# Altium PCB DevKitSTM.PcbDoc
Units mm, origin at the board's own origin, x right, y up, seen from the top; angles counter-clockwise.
Board outline 101.01 x 77.01 mm, 2 copper layers (Top Layer, Bottom Layer), stack 1.571 mm thick; 95 components, 87 nets, 365 pads, 247 vias.
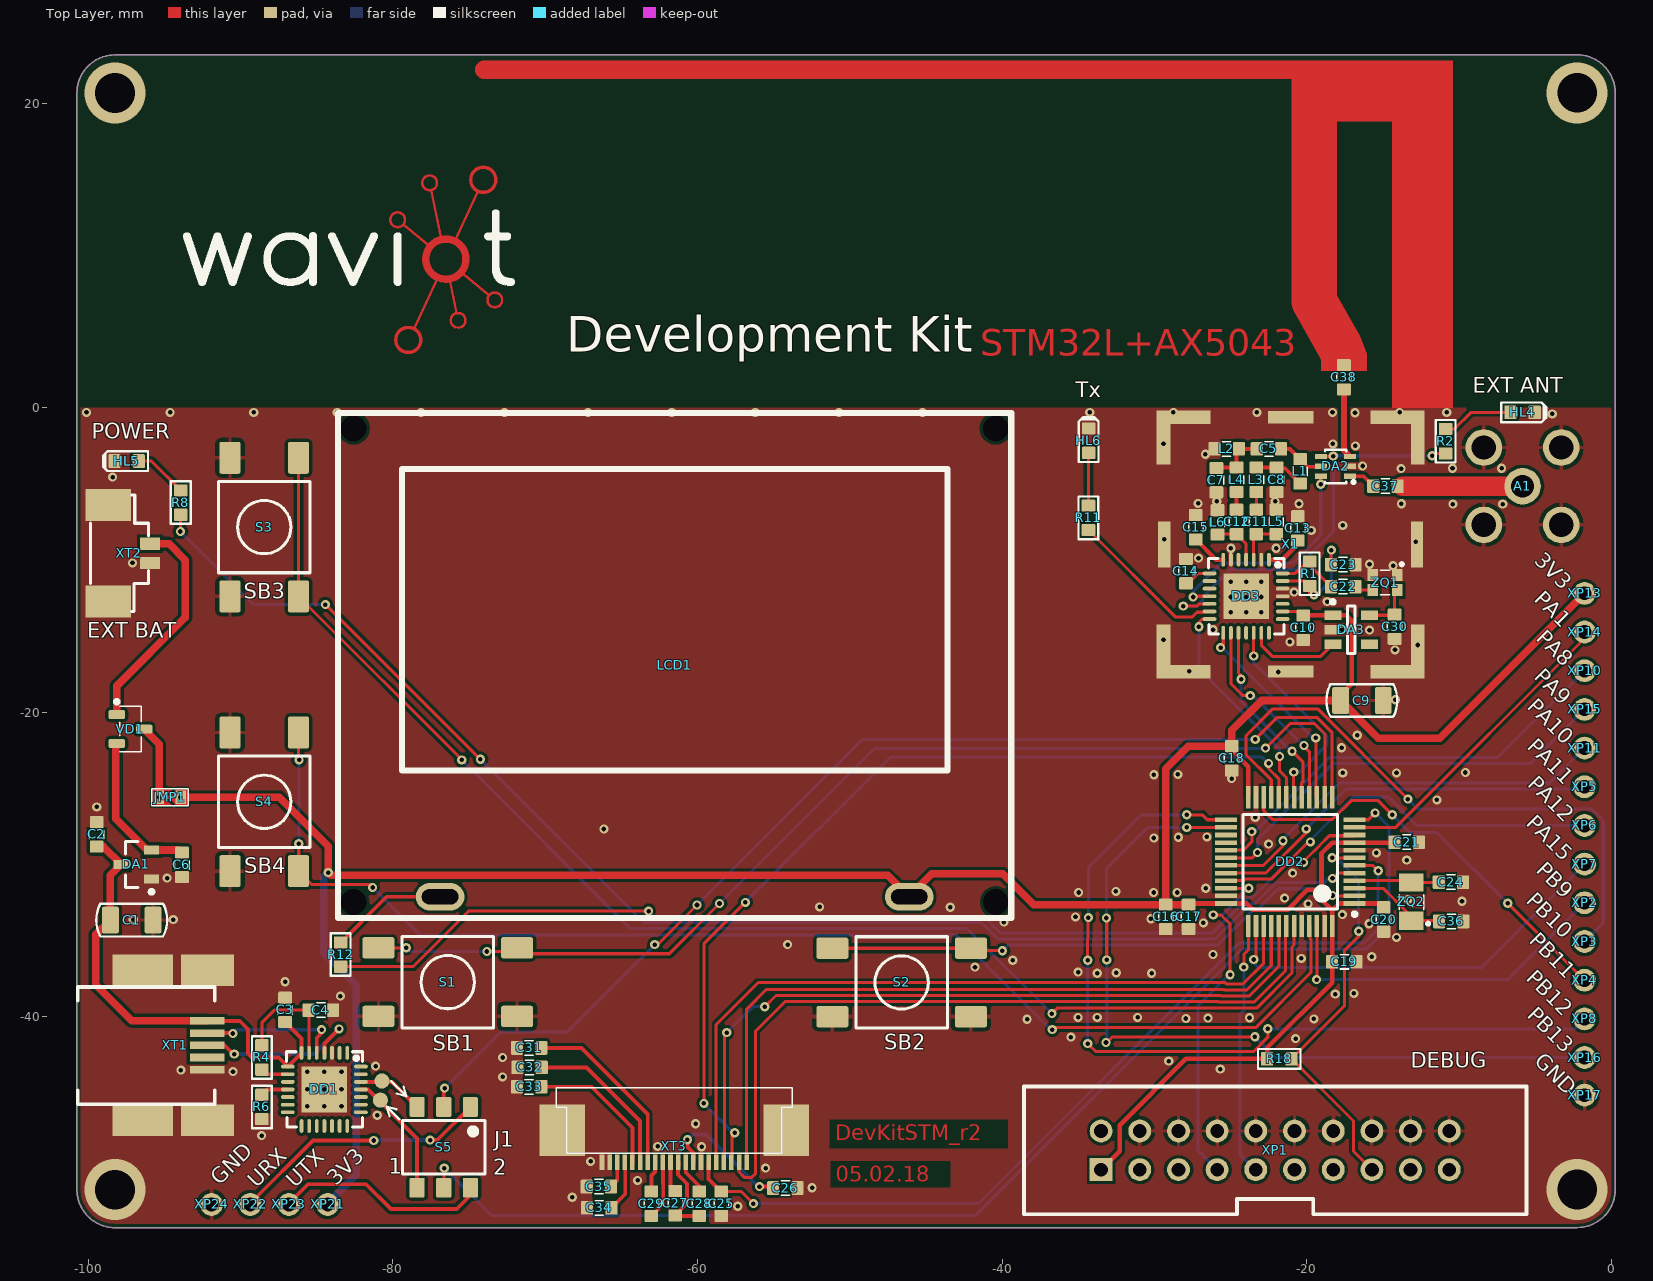
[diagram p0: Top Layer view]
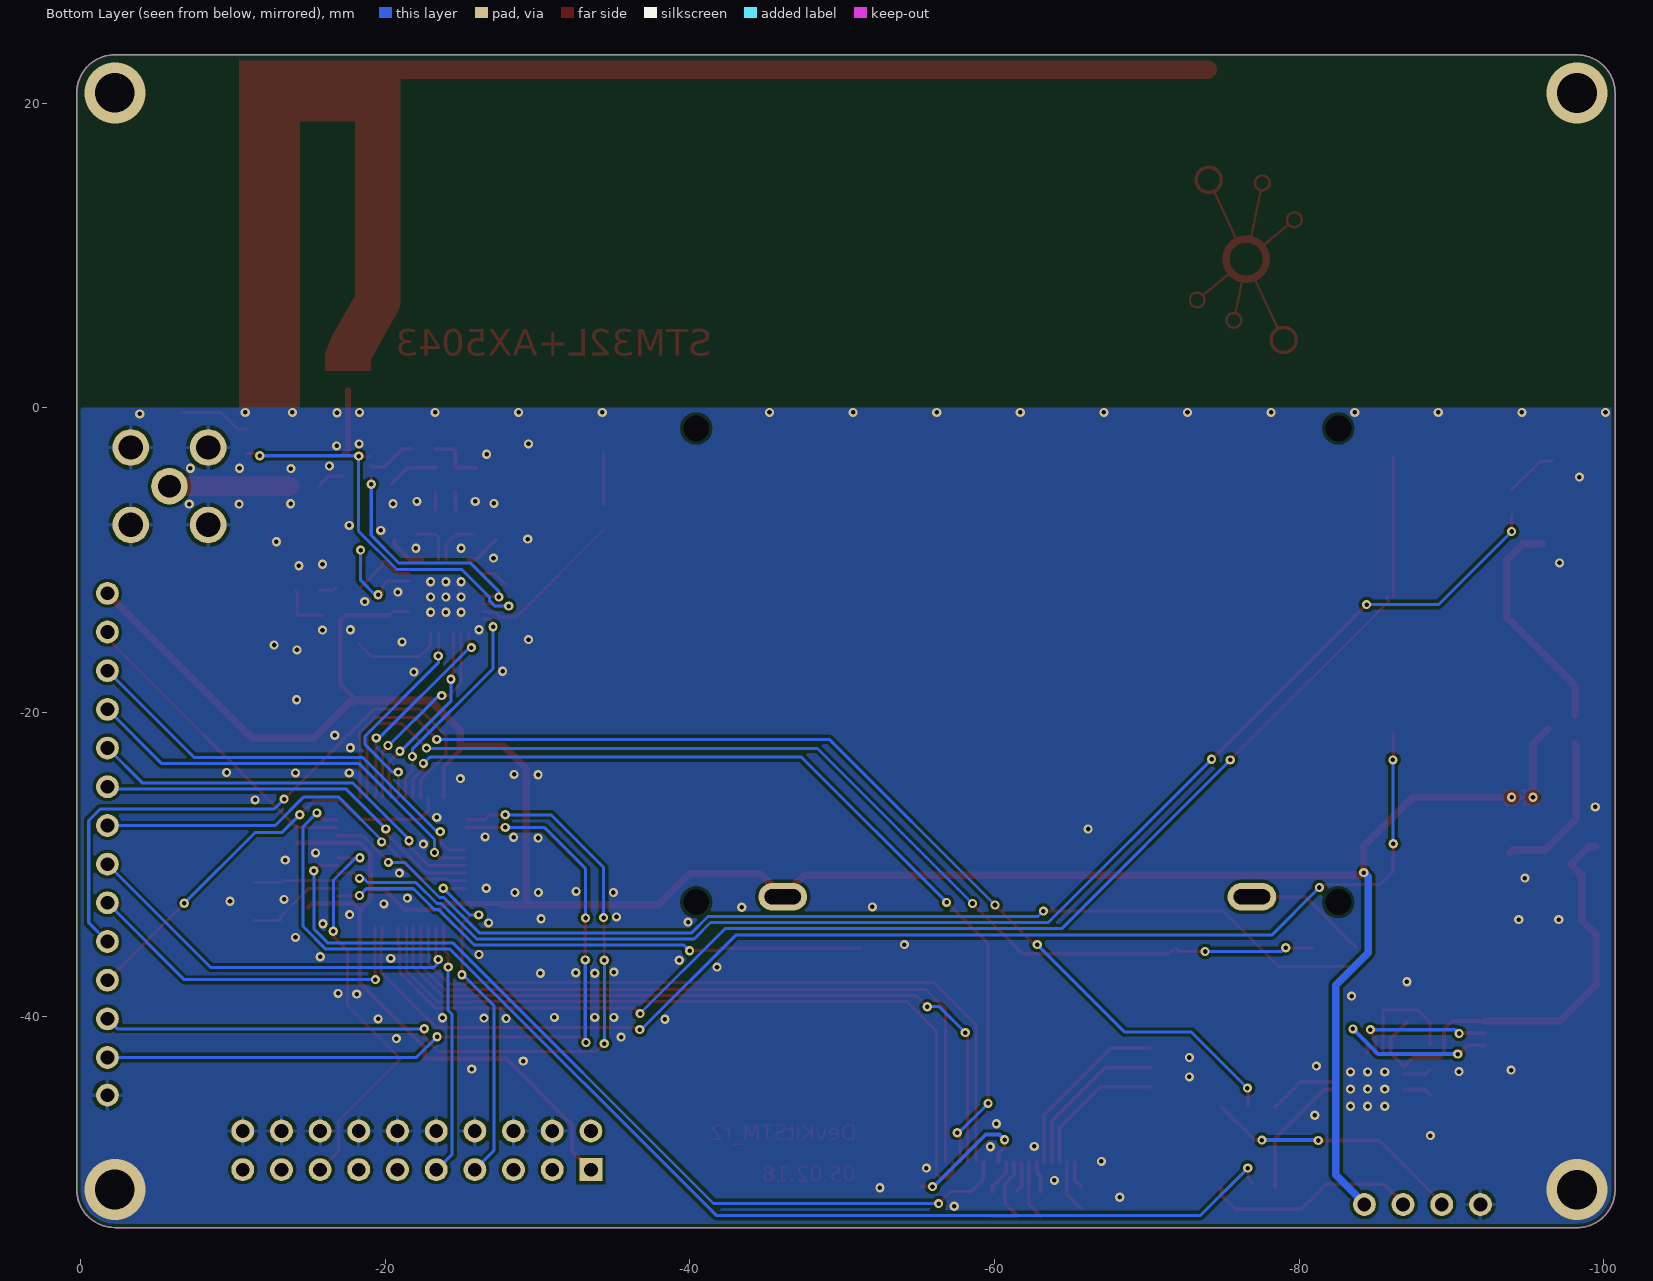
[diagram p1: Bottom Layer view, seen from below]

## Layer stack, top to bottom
Top Solder: solder mask 0.0102, Solder Resist, Dk 3.5
Top Layer: signal copper 0.0356
Dielectric 1: dielectric 1.5, FR-4, Dk 4.8
Bottom Layer: signal copper 0.0356
Bottom Solder: solder mask 0.0102, Solder Resist, Dk 3.5

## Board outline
-100.742,-51.334 -100.747,20.667 -100.742,20.667 cw(c-98.242,20.667) -98.242,23.167 -98.247,23.166 -2.242,23.166 -2.242,23.173 cw(c-2.242,20.673) 0.258,20.673 0.258,-51.328 cw(c-2.242,-51.328) -2.242,-53.828 -2.242,-53.834 -98.242,-53.834 cw(c-98.242,-51.334)

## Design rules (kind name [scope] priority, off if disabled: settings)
Clearance [All] p1: gap=0.2 ignorepadtopadclearanceinfootprint=FALSE except(0: Arc-Hole Track-Hole SMDPad-Hole THPad-Hole Via-Hole Fill-Hole Poly-Hole Region-Hole Text-Hole)
PolygonConnect PolygonConnect_1 [(HasFootprint('Cap_1206') OR HasFootprint('BH2-10') OR HasFootprint('FSM_Button') OR HasFootprint('HDR1X1') OR HasFootprint('LCD_JHD')) OR HasFootprint('SMA_Str')OR HasFootprint('BH-20')] p1: connectstyle=Relief reliefconductorwidth=0.254 reliefentries=4 polygonreliefangle="90 Angle" airgapwidth=0.254
PolygonConnect [All] p2: connectstyle=Direct reliefconductorwidth=0.3 reliefentries=4 polygonreliefangle="90 Angle" airgapwidth=0.2
RoomDefinition DevKitSTM_r1 [InComponentClass('DevKitSTM_r1')] p1: confinementstyle=ConfineIn formatcopy=TRUE lockcomponents=FALSE outline 1.425,-54.825 14.275,-54.825 14.275,24.75 1.425,24.75
RoutingVias [All] p1: holewidth=0.3 width=0.6 viastyle="Through Hole" minholewidth=0.3 minwidth=0.6 maxholewidth=1 maxwidth=1.5
SolderMaskExpansion [All] p1: expansion=0.102
Width [All] p1: maxlimit=5 minlimit=0.15 preferedwidth=0.3
30 further rules are at their usual default settings.

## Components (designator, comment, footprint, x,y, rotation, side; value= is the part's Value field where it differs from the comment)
A1 "SMA" SMA_STR -5.825,-5.15 r90 top net-tie
C1 "10 uF" CAP_1206 -97.142,-33.634 r180 top
C2 "0.1 uF" CAP_0603 -99.442,-28.009 r90 top
C3 "0.1 uF" CAP_0603 -87.072,-39.534 r90 top
C4 "0.1 uF" CAP_0603 -84.725,-39.55 r0 top
C5 "Nominal" CAP_0603 -22.475,-2.7 r180 top value="2.7 pF"
C6 "0.1 uF" CAP_0603 -93.842,-30.009 r270 top
C7 "Nominal" CAP_0603 -25.925,-4.75 r270 top value="3.6 pF"
C8 "Nominal" CAP_0603 -21.975,-4.725 r270 top value="6.2 pF"
C9 "10 uF" Cap_1206 -16.375,-19.221 r180 top
C10 "0.1uF" CAP_0603 -20.225,-14.45 r90 top
C11 "Nominal" CAP_0603 -23.3,-7.5 r270 top value="2.7 pF"
C12 "Nominal" CAP_0603 -24.6,-7.5 r270 top value="2.7 pF"
C13 "0.1uF" CAP_0603 -20.575,-7.925 r270 top
C14 "39 pF" CAP_0603 -27.925,-10.725 r270 top
C15 "0.1uF" CAP_0603 -27.275,-7.85 r270 top
C16 "Nominal" CAP_0603 -29.25,-33.425 r270 top value="4.7 uF"
C17 "Nominal" CAP_0603 -27.75,-33.425 r270 top value="0.1 uF"
C18 "Nominal" CAP_0603 -24.925,-23.019 r270 top value="0.1 uF"
C19 "Nominal" CAP_0603 -17.525,-36.375 r0 top value="0.1 uF"
C20 "Nominal" CAP_0603 -14.946,-33.6 r270 top value="0.1 uF"
C21 "Nominal" CAP_0603 -13.425,-28.525 r0 top value="0.1 uF"
C22 "1000pF" CAP_0603 -17.6,-11.75 r0 top
C23 "1000pF" CAP_0603 -17.6,-10.3 r0 top
C24 "7.5 pF" CAP_0603 -10.525,-31.15 r180 top
C25 "1uF" CAP_0603 -58.428,-52.259 r270 top
C26 "1uF" CAP_0603 -54.228,-51.234 r0 top
C27 "1uF" CAP_0603 -61.453,-52.234 r270 top
C28 "1uF" CAP_0603 -59.872,-52.259 r270 top
C29 "1uF" CAP_0603 -63.022,-52.259 r90 top
C30 "1uF" CAP_0603 -14.225,-14.375 r90 top
C31 "1uF" CAP_0603 -71.047,-42.034 r180 top
C32 "1uF" CAP_0603 -71.022,-43.309 r180 top
C33 "1uF" CAP_0603 -71.047,-44.584 r180 top
C34 "1uF" CAP_0603 -66.447,-52.534 r180 top
C35 "1uF" CAP_0603 -66.472,-51.134 r180 top
C36 "7.5 pF" CAP_0603 -10.5,-33.725 r180 top
C37 "Nominal" CAP_0603 -14.825,-5.15 r180 top value="330 pF"
C38 "Nominal" CAP_0603 -17.55,2 r270 top value="3.6 pF"
DA1 "AP2210" SOT23_L -96.842,-29.984 r180 top
DA2 "MASWSS0115" SC-70 -18.1,-3.85 r90 top
DA3 "AP2127-1.8" SOT23-5AN -17.075,-14.575 r0 top
DD1 "CP2102" QFN28 -82.992,-42.359 r270 top
DD2 "STM32L071CBT6" TSQFP50P900X900X160-48N -21.075,-29.8 r180 top
DD3 "AX5043-1-TA05" QFN28 -22.475,-9.975 r270 top
HL4 "LED_0603" LED0603 -5.825,-0.3 r180 top
HL5 "LED_0603" LED0603 -97.475,-3.5 r0 top
HL6 "LED_0603" LED0603 -34.309,-2.158 r270 top
JMP1 "STD_RES" JMP_PCB -94.625,-25.575 r0 top value="PCB Jumper"
L1 "STD_IND" IND_0603 -20.425,-4.175 r270 top value="12 nH"
L2 "STD_IND" IND_0603 -25.25,-2.7 r0 top value="12 nH"
L3 "STD_IND" IND_0603 -23.3,-4.725 r270 top value="18 nH"
L4 "STD_IND" IND_0603 -24.6,-4.725 r270 top value="18 nH"
L5 "STD_IND" IND_0603 -22,-7.5 r90 top value="18 nH"
L6 "STD_IND" IND_0603 -25.85,-7.525 r90 top value="18 nH"
LCD1 "LCD_JHD" LCD_JHD -83.592,-33.509 r0 top locked
R1 "1k" RES_0603 -19.8,-10.9 r270 top
R2 "1k" RES_0603 -10.875,-2.2 r90 top
R4 "10k" RES_0603 -88.597,-42.659 r90 top
R6 "10k" RES_0603 -88.597,-45.909 r90 top
R8 "100" RES_0603 -93.925,-6.225 r90 top
R11 "1k" RES_0603 -34.325,-7.225 r90 top
R12 "20" RES_0603 -83.425,-35.9 r90 top
R18 "1k" RES_0603 -21.8,-42.75 r180 top
S1 "SMD Button" FSM_BUTTON -76.392,-37.709 r270 top locked
S2 "SMD Button" FSM_BUTTON -46.592,-37.734 r270 top
S3 "SMD Button" FSM_BUTTON -88.442,-7.834 r180 top locked
S4 "SMD Button" FSM_Button -88.442,-25.875 r180 top locked
S5 "CAS-220" CAS-220 -76.653,-48.559 r180 top
VD1 "PMEG2005CT" SOT23 -97.225,-21.1 r0 top
X1 "STD_CON1" BMI-S-202-F -21.05,-8.975 r0 top locked
XP1 "Debug Connector" BH-20 -22.065,-48.755 r0 top
XP2 "PLS-1" HDR1X1#1 -1.75,-32.505 r180 top
XP3 "PLS-1" HDR1X1#1 -1.75,-35.045 r180 top
XP4 "PLS-1" HDR1X1#1 -1.75,-37.585 r180 top
XP5 "PLS-1" HDR1X1#1 -1.75,-24.885 r180 top
XP6 "PLS-1" HDR1X1#1 -1.75,-27.425 r180 top
XP7 "PLS-1" HDR1X1#1 -1.75,-29.965 r180 top
XP8 "PLS-1" HDR1X1#1 -1.75,-40.125 r180 top
XP10 "PLS-1" HDR1X1#1 -1.75,-17.265 r180 top
XP11 "PLS-1" HDR1X1#1 -1.75,-22.345 r180 top
XP13 "PLS-1" HDR1X1#2 -1.75,-22.562 r180 top
XP14 "PLS-1" HDR1X1#1 -1.75,-14.725 r180 top
XP15 "PLS-1" HDR1X1#1 -1.75,-19.805 r180 top
XP16 "PLS-1" HDR1X1#1 -1.75,-42.665 r180 top
XP17 "PLS-1" HDR1X1#3 -1.75,-50.492 r180 top
XP21 "PLS-1" HDR1X1#4 -89.679,-52.334 r90 top
XP22 "PLS-1" HDR1X1#5 -89.359,-52.334 r90 top
XP23 "PLS-1" HDR1X1#1 -86.819,-52.309 r90 top
XP24 "PLS-1" HDR1X1#6 -91.753,-52.359 r90 top
XT1 "Molex_MINIUSB" MOLEX_MINIUSB -96.417,-46.784 r0 top
XT2 "Molex053047" MOLEX0533980271 -95.942,-8.934 r270 top
XT3 "Molex0527462071" MOLEX_0527462071 -56.767,-49.534 r180 top locked
ZQ1 "NT2016SA-26MHz" NT2016SA -14.85,-11.475 r0 top
ZQ2 "KX-327NHT" KX-327NHT -13.125,-32.475 r90 top

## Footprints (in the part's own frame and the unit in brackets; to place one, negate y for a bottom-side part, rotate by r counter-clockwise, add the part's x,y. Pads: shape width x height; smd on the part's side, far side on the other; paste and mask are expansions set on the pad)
BH-20 [mm]
  rect 1.5x1.5 hole 0.9: 1(-11.43,-1.27)
  round 1.5 hole 0.9: 2(-11.43,1.27) 3(-8.89,-1.27) 5(-6.35,-1.27) 7(-3.81,-1.27) 9(-1.275,-1.27) 11(1.27,-1.27) 13(3.81,-1.27) 15(6.35,-1.27) 17(8.885,-1.27) 19(11.43,-1.27) G(-8.89,1.27) G(-6.35,1.27) G(-3.81,1.27) G(-1.275,1.27) G(1.27,1.27) G(3.81,1.27) G(6.35,1.27) G(8.885,1.27) G(11.43,1.27)
  silkscreen extent -16.5,-4.2 16.5,4.2, body extent -16.51,-4.8 16.51,4.8, height 9.2
BMI-S-202-F [mm]
  rect 0.9x0.9 smd mask+0.05: 1(-8.35,-8.35) 1(-8.35,8.35) 1(8.35,-8.35) 1(8.35,8.35)
  rect 0.9x2.7 smd mask+0.05: 1(-8.35,-6.6) 1(-8.35,6.6) 1(8.35,-6.6) 1(8.35,6.6)
  rect 0.8x3 smd mask+0.05: 1(-8.3,0) 1(8.3,0)
  rect 2.7x0.9 smd mask+0.05: 1(-6.6,8.35) 1(-6.6,-8.35) 1(6.6,8.35) 1(6.6,-8.35)
  rect 3x0.8 smd mask+0.05: 1(0,-8.35) 1(0,8.35)
  body extent -8.25,-8.25 8.25,8.25, height 3.7
CAP_0603 [mm]
  rrect20% 0.8x0.9 smd: 1(-0.8,0) 2(0.8,0)
  Top Layer pour cut-out: -0.425,0.65 0.45,0.65 0.45,-0.65 -0.425,-0.65
  silkscreen extent -0.28,-0.48 0.28,0.48, body extent -0.88,-0.48 0.87,0.48, height 0.85
CAP_1206 [mm]
  rrect20% 1.1x1.75 smd: 1(-1.4,0) 2(1.4,0)
  silkscreen extent -2.33,-1.07 2.33,1.08, body extent -1.65,-0.9 1.65,0.9, height 1.35
Cap_1206 [mm]
  rrect20% 1.1x1.75 smd: 1(-1.4,0) 2(1.4,0)
  silkscreen extent -2.33,-1.07 2.33,1.08, body extent -1.65,-0.9 1.65,0.9, height 1.35
CAS-220 [mm]
  rrect20% 1x1.3 smd: 1(-1.75,-2.65) 2(0,-2.65) 3(1.75,-2.65) 4(-1.75,2.65) 5(0,2.65) 6(1.75,2.65)
  silkscreen extent -2.7,-1.75 2.7,1.75, body extent -2.7,-2.72 2.7,2.88, height 2.5
FSM_BUTTON [mm]
  rrect20% 1.4x2.1 smd: 1(-2.25,4.55) 1(-2.25,-4.55) 2(2.25,4.55) 2(2.25,-4.55)
  silkscreen extent -3,-3 3,3, body extent -3,-3 3,3, height 5
FSM_Button [mm]
  rrect20% 1.4x2.1 smd: 1(-2.25,4.55) 1(-2.25,-4.55) 2(2.25,4.55) 2(2.25,-4.55)
  silkscreen extent -3,-3 3,3, body extent -3,-3 3,3, height 5
HDR1X1#1 [mm]
  round 1.5 hole 0.9 mask+0: 1(0,0)
HDR1X1#2 [mm]
  round 1.5 hole 0.9 mask+0: 1(0,-10.377)
HDR1X1#3 [mm]
  round 1.5 hole 0.9 mask+0: 1(0,-5.362)
HDR1X1#4 [mm]
  round 1.5 hole 0.9 mask+0: 1(0.025,-5.4)
HDR1X1#5 [mm]
  round 1.5 hole 0.9 mask+0: 1(0.025,0)
HDR1X1#6 [mm]
  round 1.5 hole 0.9 mask+0: 1(0.05,0.146)
IND_0603 [mm]
  rrect20% 0.8x0.9 smd: 1(-0.8,0) 2(0.8,0)
  Top Layer pour cut-out: -0.425,0.65 0.45,0.65 0.45,-0.65 -0.425,-0.65
  silkscreen extent -0.28,-0.48 0.28,0.48, body extent -0.88,-0.48 0.87,0.48, height 0.85
JMP_PCB [mm]
  rect 0.6x0.9 smd: 1(-0.7,0)
  rect 0.7x0.9 smd: 2(0.7,0)
  Top Layer region: -0.1,0 0.408,0.508 1.143,0.508 1.143,-0.508 0.408,-0.508
  Top Layer region: 0.108,0.508 -0.4,0 0.108,-0.508 -1.143,-0.508 -1.143,0.508
  silkscreen extent -1.2,-0.55 1.2,0.55
KX-327NHT [mm]
  rect 1.2x1.6 smd mask+0.05: 1(-1.2,0) 2(1.3,0)
  silkscreen extent -1.5,-1.2 0.5,0.8, body extent -1.6,-0.75 1.6,0.75, height 0.8
LCD_JHD [mm]
  oval 3.2x1.8 hole 1 slot 2.4 at 0 deg: A(37.5,1.4) K(6.7,1.4)
  round 0 hole 1.7 unplated: ""(1.02,1.05) ""(1.02,32.15) ""(43.18,1.05) ""(43.18,32.15)
  silkscreen extent 0,0 44.2,33.18, body extent 0,0 44.23,33.18, height 4
LED0603 [mm]
  rrect20% 0.8x0.9 smd: A(0.8,0) C(-0.8,0)
  silkscreen extent -1.55,-0.65 1.4,0.65, body extent -0.8,-0.4 0.8,0.4, height 0.28
MOLEX0533980271 [mm]
  rect 0.8x1.3 smd mask+0.05: 1(0,0) 2(1.25,0)
  rect 2.1x3 smd mask+0.05: 3(-2.55,-2.75) 3(3.8,-2.75)
  silkscreen extent -3.2,-3.9 4.45,-0.1, body extent -3.18,-3.95 4.47,0.25, height 4.6
MOLEX_0527462071 [mm]
  rect 0.3x1 smd mask+0.05: 1(0,0) 2(0.5,0) 3(1,0) 4(1.5,0) 5(2,0) 6(2.5,0) 7(3,0) 8(3.5,0) 9(4,0) 10(4.5,0) 11(5,0) 12(5.5,0) 13(6,0) 14(6.5,0) 15(7,0) 16(7.5,0) 17(8,0) 18(8.5,0) 19(9,0) 20(9.5,0)
  rect 3x3.4 smd mask+0.05: 21(-2.6,-2.1) 22(12.1,-2.1)
  silkscreen extent -3,-4.9 12.5,-0.6, body extent -3.3,-6.42 12.8,0.18, height 2
MOLEX_MINIUSB [mm]
  rect 2.25x0.5 smd mask+0.05: 1(4.225,6.525) 2(4.225,5.725) 3(4.225,4.925) 4(4.225,4.125) 5(4.225,3.325)
  rect 4x2.05 smd mask+0.05: 5(0,0) 5(0,9.85)
  rect 3.5x2.05 smd mask+0.05: 5(4.25,0) 5(4.25,9.85)
  silkscreen extent -4.28,1.05 4.72,8.75, body extent -4.27,0 4.72,9.9, height 4.05
NT2016SA [mm]
  rect 0.7x0.8 smd mask+0.05: 1(0.795,0.5) 2(-0.805,0.5) 3(-0.805,-0.5) 4(0.795,-0.5)
  silkscreen extent -0.31,-0.8 1.19,1.3, body extent -1,-0.8 1,0.8, height 0.8
QFN28 [mm]
  oval 0.9x0.25 smd: 1(0,0) 2(0,-0.5) 3(0,-1) 4(0,-1.5) 5(0,-2) 6(0,-2.5) 7(0,-3) 15(4.8,-3) 16(4.8,-2.5) 17(4.8,-2) 18(4.8,-1.5) 19(4.8,-1) 20(4.8,-0.5) 21(4.8,0)
  oval 0.25x0.9 smd: 8(0.9,-3.9) 9(1.4,-3.9) 10(1.9,-3.9) 11(2.4,-3.9) 12(2.9,-3.9) 13(3.4,-3.9) 14(3.9,-3.9) 22(3.9,0.9) 23(3.4,0.9) 24(2.9,0.9) 25(2.4,0.9) 26(1.9,0.9) 27(1.4,0.9) 28(0.9,0.9)
  rect 3x3 smd mask+0: 29(2.4,-1.5)
  silkscreen extent -0.08,-3.98 4.88,1, body extent -0.1,-3.95 4.9,1.05, height 1
RES_0603 [mm]
  rrect20% 0.8x0.9 smd: 1(-0.8,0) 2(0.8,0)
  Top Layer pour cut-out: -0.425,0.65 0.45,0.65 0.45,-0.65 -0.425,-0.65
  silkscreen extent -1.4,-0.65 1.4,0.65, body extent -0.85,-0.48 0.85,0.48, height 0.6
SC-70 [mm]
  rect 0.35x0.8 smd mask+0.05: 1(-0.65,-0.95) 2(0,-0.95) 3(0.65,-0.95) 4(0.65,0.95) 5(0,0.95) 6(-0.65,0.95)
  silkscreen extent -1.12,-1.27 1.1,0.7, body extent -1,-1.05 1,1.05, height 0.92
SMA_STR [mm]
  round 2.4 hole 1.5: 1(0,0)
  round 2.4 hole 1.6: 2(-2.54,-2.54) 2(-2.54,2.54) 2(2.54,-2.54) 2(2.54,2.54)
  body extent -3.17,-3.18 3.18,3.18, height 10.22
SOT23 [mm]
  rrect50% 1.1x0.6 smd: 1(-0.9,0.95) 2(-0.9,-0.95) 3(0.9,0)
  silkscreen extent -1.02,-1.5 0.7,1.92, body extent -1.25,-1.5 1.25,1.5, height 1.06
SOT23-5AN [mm]
  rect 1.1x0.65 smd: 1(-1.2,0.95) 2(-1.2,0) 3(-1.2,-0.95) 4(1.2,-0.95) 5(1.2,0.95)
  silkscreen extent -1.32,-1.55 0.25,1.95, body extent -1.5,-1.5 1.5,1.5, height 1.3
SOT23_L [mm]
  rect 1x0.6 smd: 1(-1,0.95) 2(-1,-0.95) 3(1,0)
  silkscreen extent -1.13,-1.5 0.7,1.92, body extent -1.32,-1.5 1.32,1.5, height 1.08
TSQFP50P900X900X160-48N [mm]
  rect 1.45x0.3 smd: 1(-4.225,2.75) 2(-4.225,2.25) 3(-4.225,1.75) 4(-4.225,1.25) 5(-4.225,0.75) 6(-4.225,0.25) 7(-4.225,-0.25) 8(-4.225,-0.75) 9(-4.225,-1.25) 10(-4.225,-1.75) 11(-4.225,-2.25) 12(-4.225,-2.75) 25(4.225,-2.75) 26(4.225,-2.25) 27(4.225,-1.75) 28(4.225,-1.25) 29(4.225,-0.75) 30(4.225,-0.25) 31(4.225,0.25) 32(4.225,0.75) 33(4.225,1.25) 34(4.225,1.75) 35(4.225,2.25) 36(4.225,2.75)
  rect 0.3x1.45 smd: 13(-2.75,-4.225) 14(-2.25,-4.225) 15(-1.75,-4.225) 16(-1.25,-4.225) 17(-0.75,-4.225) 18(-0.25,-4.225) 19(0.25,-4.225) 20(0.75,-4.225) 21(1.25,-4.225) 22(1.75,-4.225) 23(2.25,-4.225) 24(2.75,-4.225) 37(2.75,4.225) 38(2.25,4.225) 39(1.75,4.225) 40(1.25,4.225) 41(0.75,4.225) 42(0.25,4.225) 43(-0.25,4.225) 44(-0.75,4.225) 45(-1.25,4.225) 46(-1.75,4.225) 47(-2.25,4.225) 48(-2.75,4.225)
  silkscreen extent -4.35,-3.1 3.1,3.57, body extent -3.5,-3.5 3.5,3.5, height 1.6

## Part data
A1: library part SMA_Str, "CONN SMA JACK STR 50 OHM PCB", PartNumber=5-1814832-1
C1 C9: library part "Cap 1206", "CAP CER 10UF 16V Y5V 1206", Code Value="code of resistance marked on chip", Package=Footprint, PartNumber=CL31F106ZOHNNNE
C2 C3 C4 C6 C10 C13 C15: library part "Cap 0603", "CAP CER 0603 0.1 uF 16 V 10% X7R", Code Value="code of resistance marked on chip", Package=Footprint, PartNumber=CC0603KRX7R7BB104
C5 C11 C12: library part GRM1885C1H2R7CA01D, "CAP CER 2.7PF 50V NPO 0603", Manufacturer=MURATA, PartNumber=CC0603BRNPO9BN2R7, Tolerance="+/- 0.25 пФ"
C7 C38: library part CL10C3R6CB8NNNC, "CAP CER 3.6PF 50V NPO 0603", Manufacturer=Samsung, PartNumber=CC0603BRNPO9BN3R6, Tolerance="+/- 0.25 пФ"
C8: library part CL10C6R2CB8NNNC, "CAP CER 6.2PF 50V NPO 0603", Manufacturer=Samsung, Tolerance="+/- 0.25 пФ"
C14: library part "Cap 0603", "CAP CER 39PF 50V C0G/NPO 0603", Code Value="code of resistance marked on chip", Package=Footprint, PartNumber=CC0603JRNPO9BN390
C16: library part CC0603KRX5R6BB475, "CAP CER 0603 4.7 uF 10 V 10% X5R", Manufacturer=YAGEO, Tolerance=10%
C17 C18 C19 C20 C21: library part CC0603KRX7R7BB104, "CAP CER 0603 0.1 uF 16 V 10% X7R", Manufacturer=YAGEO, Tolerance=10%
C22 C23: library part "Cap 0603", "CAP CER 1000PF 50V X7R 0603", Code Value="code of resistance marked on chip", Package=Footprint, PartNumber=CC0603KRX7R9BB102
C24 C36: library part "Cap 0603", "CAP CER 7.5PF 50V NPO 0603", Code Value="code of resistance marked on chip", Package=Footprint, PartNumber=CC0603CRNPO9BN7R5
C25 C26 C27 C28 C29 C31 C32 C33 C34 C35: library part "Cap 0805", "CAP CER 1UF 16V X7R 0603", Code Value="code of resistance marked on chip", Package=Footprint, PartNumber=CC0603KRX7R7BB105
C30: library part "Cap 0603", "CAP CER 1UF 16V X7R 0603", Code Value="code of resistance marked on chip", Package=Footprint, PartNumber=CC0603KRX7R7BB105
C37: library part GRM1885C1H2R7CA01D, "CAP CER 330PF 50V NPO 0603", Manufacturer=MURATA, PartNumber=CC0603JRNPO9BN331, Tolerance="+/- 0.25 пФ"
DA1: "IC REG LDO 3.3V 0.3A SOT23", PartNumber=AP2210N-3.3TRG1
DA2: "GaAs SPDT Switch  DC - 3.0 GHz", PartNumber=MASWSS0115TR-3000
DA3: library part AP2127, "IC REG LINEAR 1.8V 300MA SOT23-5", PartNumber=AP2127K-1.8TRG1
DD1: "IC USB-TO-UART BRIDGE 28VQFN", PartNumber=CP2102-GMR
DD2: "IC MCU 32BIT 128KB FLASH 48LQFP", Digi-Key Part Number=STM32L071CBT6-ND, Manufacturer=STMicroelectronics, Operating Temperature="-40°C ~ 85°C (TA)", Package / Case=48-LQFP, Voltage - Supply (Vcc/Vdd)="1.65 V ~ 3.6 V"
DD3: library part AX5043, "IC AXSEM RF Tranceiver"
HL4: "LED GREEN CLEAR 0603 SMD", PartNumber=APT1608CGCK
HL5: "LED 527NM BLU/GRN TRANSP RA SMD", PartNumber=SMLE13EC8TT86
HL6: "LED 1.6X0.8MM 630NM RED CLR SMD", PartNumber=APT1608SURCK
JMP1: library part JMP_PCB, "NoName  PCB Jumper", Manufacturer=NoName
L1: library part LQW18AN12NG00, "FIXED IND 18NH 650MA 160 MOHM", Current="650 мА", Manufacturer=MURATA, Tolerance=2%
L2: library part LQW18AN12NG00, "FIXED IND 12NH 650MA 160 MOHM", Current="650 мА", Manufacturer=MURATA, Tolerance=2%
L3 L4 L5 L6: library part LQW18AN18NG00, "FIXED IND 18NH 550MA 160 MOHM", Current="500 мА", Manufacturer=MURATA, Tolerance=2%
LCD1: "LCD Display", PartNumber=JHD12864
R1 R2 R11 R18: library part "Res 0603", "RES SMD 1K OHM 1% 1/10W 0603", Code Value="code of resistance marked on chip", Package=Footprint, PartNumber=RC1608F102CS
R4 R6: library part "Res 0603", "RES SMD 10 KOHM 1% 1/10W 0603", Code Value="code of resistance marked on chip", Package=Footprint, PartNumber=RC1608F103CS
R8: library part "Res 0603", "RES SMD 100 OHM 1% 1/10W 0603", Code Value="code of resistance marked on chip", Package=Footprint, PartNumber=RC1608J101CS
R12: library part "Res 0805", "RES SMD 20 OHM 1% 1/10W 0603", Code Value="code of resistance marked on chip", Package=Footprint, PartNumber=RC1608F200CS
S1 S2 S3 S4: "SWITCH TACTILE SPST-NO 0.05A 24V", PartNumber=FSM4JSMATR
S5: "SLIDE SWITCH DPDT GULLWING 6V", PartNumber=CAS-220TB
VD1: "DIODE ARRAY SCHOTTKY 20V SOT23", Current="500 мА", Manufacturer=NXP
X1: library part BMI-S-202-F, "BOARD SHIELD .65X.65\" FRAME + COVER", Manufacturer=Liard, PartNumber="BMI-S-202-F + BMI-S-202-C"
XP1: library part JTAG_BH20, "CONN 2 RAWS 20 PINS 2.54 PITCH", PartNumber=BH-20
XT1: "CONN RECEPT MINIUSB R/A 5POS SMD", PartNumber=548190572
XT2: "CONN HEADER 2POS 1.25MM VERT SMD", PartNumber=533980271
XT3: "20-pin LCD connector", PartNumber=CONN_FOR_JHD12864
ZQ1: library part NT2016, "Quartz Crystal Controlled Oscillator", PartNumber=NT2016SA-26.000000MHZ-NBG2
ZQ2: "Geyer  Quartz Crystal", Part Manufacturer="GEYER ELECTRONIC"

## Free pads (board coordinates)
  round 1 smd mask+0: 1(-80.817,-45.459) 1(-80.717,-44.209)

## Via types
v1: diameter 0.6, hole 0.3, Top Layer to Bottom Layer, tented both sides, 243 vias
v2: diameter 4, hole 2.6, Top Layer to Bottom Layer, 4 vias

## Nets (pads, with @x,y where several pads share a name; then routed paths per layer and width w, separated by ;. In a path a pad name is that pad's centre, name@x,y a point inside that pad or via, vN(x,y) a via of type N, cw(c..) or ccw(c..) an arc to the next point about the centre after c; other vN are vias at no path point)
GND: A1.2 C1.1 C2.2 C3.2 C4.2 C6.2 C7.2 C8.2 C9.1 C10.1 C13.1 C14.1 C15.1 C16.2 C17.2 C18.2 C19.2 C20.2 C21.2 C23.2 C24.1 C25.2 C26.2 C30.1 C31.2 C32.2 C33.2 C34.2 C35.2 C36.1 C38.1 DA1.1 DA2.2 DA3.2 DD1.3 DD1.29 DD2.8 DD2.23 DD2.35 DD2.44 DD2.47 DD3.2 DD3.6 DD3.25 DD3.26 DD3.29 HL4.C HL5.C HL6.C L2.1 L5.2 L6.2 R6.1 S1.2 S2.2 S3.2 S4.2 X1.1 XP1.G XP17.1 XP24.1 XT1.5 XT2.2 XT2.3 XT3.7 XT3.19 XT3.20 XT3.21 XT3.22 ZQ1.1 ZQ1.2 | length 68.5
  Top Layer w1.2: -74,22.2 -21,22.2
  Top Layer w3: -19.5,19 -19.5,7 -17.791,3.933
  other v1: -57.35,-52.425 -68.217,-51.834 -52.467,-51.209 -63.925,-50.725 -55.525,-49.925 -67.017,-49.484 -59.725,-48.525 -62.6,-48.5 -88.617,-47.784 -60.117,-47.009 -81.025,-46.45 -85.617,-45.859 -84.492,-45.859 -83.367,-45.859 -85.617,-44.734 -84.492,-44.734 -83.367,-44.734 -72.792,-43.934 -85.617,-43.609 -84.492,-43.609 -83.367,-43.609 -90.492,-43.584 -93.917,-43.484 -25.675,-43.425 -81.125,-43.225 -29.05,-42.9 -72.792,-42.659 -20.725,-41.425 -35.475,-41.325 -38.35,-40.15 -19.525,-40.125 -27.925,-40.1 -26.475,-40.075 -23.75,-40.05 -35,-40.025 -33.75,-40.025 -31.1,-40.025 -83.442,-38.634 -18.125,-38.5 -16.9,-38.45 -87.067,-37.684 -33.75,-37.125 -32.5,-37.1 -30.175,-37.125 -35,-37.05 -41.775,-36.725 -39.3,-36.275 -20.35,-36.15 -15.725,-36.05 -26.15,-35.9 -54.075,-35.25 -14.1,-34.775 -15.9,-33.875 -26.775,-33.825 -39.875,-33.775 -97.042,-33.609 -94.417,-33.609 -30.225,-33.55 -35.175,-33.425 -17.65,-33.275 -43.4,-32.8 -51.975,-32.775 -19.9,-32.575 -9.8,-32.4 -13.35,-32.275 -21.45,-32.2 -34.975,-31.825 -30.05,-31.825 -28.5,-31.825 -32.525,-31.75 -26.625,-31.55 -94.817,-30.884 -20.925,-30.55 -13.425,-29.7 -15.425,-29.225 -22.5,-28.65 -30.025,-28.25 -28.425,-28.2 -26.55,-28.175 -66.142,-27.659 -23.375,-26.9 -99.442,-26.209 -11.45,-25.75 -24.925,-24.35 -30.025,-24.1 -28.45,-24.075 -17.625,-23.975 -14.1,-23.975 -9.575,-23.95 -17.7,-22.325 -16.675,-21.5 -14.175,-19.175 -21.875,-17.35 -27.7,-17.3 -14.2,-15.9 -12.7,-15.575 -21.1,-15.375 -29.4,-15.225 -15.875,-14.6 -26.15,-14.575 -17.7,-14.575 -24.975,-13.425 -23.975,-13.425 -22.975,-13.425 -18.65,-12.725 -24.975,-12.425 -23.975,-12.425 -22.975,-12.425 -20.825,-12.1 -24.975,-11.425 -23.975,-11.425 -22.975,-11.425 -14.325,-10.375 -15.875,-10.275 -97.092,-10.184 -27.1,-9.875 -24.975,-9.225 -22,-9.225 -12.85,-8.8 -29.35,-8.625 -19.7,-8.05 -17.625,-7.725 -10.4,-6.325 -7.125,-6.325 -20.5,-6.3 -13.775,-6.3 -27.125,-6.275 -25.9,-6.15 -22.075,-6.15 -98.4,-4.55 -13.8,-4 -10.425,-3.975 -7.2,-3.975 -16.325,-3.825 -26.65,-3.05 -16.8,-2.5 -29.4,-2.375 -18.275,-2.375 -3.875,-0.4 -16.825,-0.325 -100.113,-0.3 -94.623,-0.3 -89.134,-0.3 -83.645,-0.3 -78.156,-0.3 -72.667,-0.3 -67.178,-0.3 -61.688,-0.3 -56.199,-0.3 -50.71,-0.3 -45.221,-0.3 -34.243,-0.3 -28.753,-0.3 -23.264,-0.3 -18.3,-0.3 -13.9,-0.3 -10.8,-0.3
  other v2: -98.242,-51.334 -2.242,-51.328
NetA1_1: A1.1 C37.1 | length 7.9
  Top Layer w1.3: C37.1@-13.7,-5.15 A1.1
NetC1_2: C1.2 C2.1 C3.1 DA1.3 DD1.7 DD1.8 XT1.1 | length 30.2
  Top Layer w0.25: XT1.1 -90.053,-40.259 -89.503,-40.809 -89.503,-42.39 -89.234,-42.659 -87.492,-42.659 DD1.8 DD1.7 -85.992,-41.414 C3.1
  Top Layer w0.5: C2.1 -99.017,-28.809 DA1.3 -98.542,-30.684 C1.2 -99.492,-34.584 -99.492,-37.896 -97.128,-40.259 XT1.1
NetC4_1: C4.1 DD1.6 R4.2 | length 7.7
  Top Layer w0.2: R4.2 -88.597,-40.372 -87.775,-39.55 C4.1 ; DD1.6 C4.1@-85.492,-39.55
NetC5_1: C5.1 DA2.5 L1.1 | length 3.1
  Top Layer w0.25: C5.1 -21.1,-2.7 L1.1 -19.925,-3.875 -19.075,-3.875 DA2.5
NetC5_2: C5.2 C7.1 L2.2 L4.1 | length 3.8
  Top Layer w0.25: C7.1 -25.9,-3.925 L4.1 -24.6,-2.85 L2.2 C5.2
NetC6_1: C6.1 DA1.2 VD1.2 | length 10.2
  Top Layer w0.5: VD1.2 -98.2,-22.125 -98.2,-26.975 -96.141,-29.034 DA1.2 -94.017,-29.034 C6.1
NetC8_1: C8.1 L1.2 L3.1 | length 3.3
  Top Layer w0.25: L3.1 -22.025,-3.925 -21.975,-3.975 -21.425,-3.975 L1.2
NetC11_1: C11.1 L3.2 | length 1.2
  Top Layer w0.2: C11.1 L3.2
NetC11_2: C11.2 DD3.3 L5.1 | length 3
  Top Layer w0.2: DD3.3 -23.475,-8.475 C11.2 L5.1
NetC12_1: C12.1 L4.2 | length 1.2
  Top Layer w0.28: C12.1 L4.2
NetC12_2: C12.2 DD3.4 L6.1 | length 3.2
  Top Layer w0.2: L6.1 -25.825,-8.3 C12.2 -23.975,-8.925 DD3.4
NetC13_2: C13.2 DD3.1 | length 2.5
  Top Layer w0.3: DD3.1@-22.425,-9.975 -21.6,-9.975 -20.575,-8.95 C13.2
NetC14_2: C14.2 DD3.8 | length 1.8
  Top Layer w0.2: C14.2 -27.775,-11.525 -27.125,-10.875 DD3.8
NetC15_2: C15.2 DD3.7 | length 2.3
  Top Layer w0.28: C15.2 -25.95,-9.975 DD3.7
NetC22_1: C22.1 DD3.28 R1.1 | length 4.3
  Top Layer w0.2: DD3.28 -20.75,-10.875 -19.975,-10.1 R1.1 -19.8,-10.35 C22.1
NetC22_2: C22.2 ZQ1.3 | length 1.2
  Top Layer w0.2: C22.2 -16.575,-11.975 ZQ1.3
NetC23_1: C23.1 DD3.27 R1.2 | length 7.2
  Top Layer w0.2: DD3.27 -20.125,-11.375 R1.2 -19.8,-12.25 -19.775,-12.275 v1(-19.525,-12.275) ; C23.1 -18.4,-9.375 v1(-18.375,-9.35)
  Bottom Layer w0.2: v1(-19.525,-12.275) -19.325,-12.275 -18.375,-11.325 v1(-18.375,-9.35)
NetC24_2: C24.2 DD2.4 ZQ2.2 | length 5.6
  Top Layer w0.2: DD2.4 -13.25,-31.05 ZQ2.2 -11.35,-31.175 C24.2
NetC25_1: C25.1 DD2.6 XT3.6 | length 58.7
  Top Layer w0.2: C25.1 -57.116,-51.459 v1(-56.325,-52.25) ; DD2.6 -15.65,-30.05 v1(-15.3,-30.4)
  Top Layer w0.25: XT3.6 -59.267,-50.646 C25.1@-58.428,-51.484
  Bottom Layer w0.2: v1(-56.325,-52.25) -41.55,-52.25 -24.45,-35.15 -16.25,-35.15 -15.3,-34.2 v1(-15.3,-30.4)
NetC26_1: C26.1 XT3.8 | length 8.8
  Top Layer w0.25: v1(-60.653,-48.059) -60.653,-48.538 -60.267,-48.924 XT3.8 ; v1@-56.053,-51.134 v1(-55.925,-51.134) C26.1@-55.178,-51.134
  Bottom Layer w0.25: v1(-60.653,-48.059) -60.319,-47.725 -59.417,-47.725 -56.008,-51.134 v1(-55.925,-51.134)
NetC27_1: C27.1 XT3.11 | length 2
  Top Layer w0.25: XT3.11 -61.767,-51.121 C27.1
NetC27_2: C27.2 C28.2 XT3.10 | length 6
  Top Layer w0.25: C28.2 -61.428,-53.059 C27.2 -61.453,-53.009 -60.678,-52.234 -60.678,-50.946 -61.267,-50.358 XT3.10@-61.267,-49.771 ; XT3.10@-61.267,-49.771 XT3.10 -61.242,-49.559 -61.242,-49.796 XT3.10@-61.267,-49.771
NetC28_1: C28.1 XT3.9 | length 2.3
  Top Layer w0.25: XT3.9 -60.767,-50.222 -59.872,-51.117 C28.1
NetC29_1: C29.1 XT3.12 | length 3.9
  Top Layer w0.25: C29.1 -62.247,-52.284 -62.247,-50.971 -62.267,-50.951 XT3.12
NetC29_2: C29.2 XT3.13 | length 2.1
  Top Layer w0.25: C29.2 -63.022,-50.399 -62.792,-50.169 -62.792,-49.559 XT3.13 XT3.13@-62.747,-49.554
NetC30_2: C30.2 DA3.5 ZQ1.4 | length 3.3
  Top Layer w0.2: DA3.5 -14.275,-13.625 C30.2 -14.225,-12.145 ZQ1.4
NetC31_1: C31.1 XT3.14 | length 11.9
  Top Layer w0.25: C31.1 -67.603,-42.034 -63.267,-46.371 XT3.14
NetC32_1: C32.1 XT3.15 | length 10.6
  Top Layer w0.25: C32.1 -67.29,-43.309 -63.767,-46.832 XT3.15
NetC33_1: C33.1 XT3.16 | length 9.4
  Top Layer w0.25: C33.1 -66.953,-44.584 -64.267,-47.271 XT3.16
NetC34_1: C34.1 XT3.17 | length 3.4
  Top Layer w0.25: C34.1 -64.742,-51.629 -64.742,-49.559 XT3.17
NetC35_1: C35.1 XT3.18 | length 1.8
  Top Layer w0.25: C35.1 -65.267,-50.729 XT3.18
NetC36_2: C36.2 DD2.3 ZQ2.1 | length 6.6
  Top Layer w0.2: DD2.3 -14.968,-31.55 -14.196,-32.323 -14.196,-32.329 -13.125,-33.4 ZQ2.1 -11.35,-33.675 C36.2
NetC37_2: C37.2 DA2.1 | length 1.8
  Top Layer w0.25: DA2.1 -16.275,-4.5 C37.2
NetC38_2: C38.2 DA2.3 | length 4.3
  Top Layer w0.4: C38.2@-17.55,1.125 -17.55,-2.8 DA2.3@-17.3,-3.05
NetDA2_4: DA2.4 DD3.12 R2.1 | length 27
  Top Layer w0.2: v1(-28.1,-13.025) -27.202,-13.026 -27.051,-12.875 DD3.12 ; DA2.4 -18.275,-3.2 v1(-18.25,-3.175) ; v1(-11.75,-3.15) -11.6,-3 R2.1
  Bottom Layer w0.2: v1(-28.1,-13.025) -27.202,-13.026 -26.85,-12.674 -26.85,-12.452 -25.024,-10.625 -20.759,-10.625 -18.225,-8.091 v1@-18.225,-3.175 ; v1(-18.25,-3.175) -18.225,-3.15 v1(-11.75,-3.15)
NetDA2_6: DA2.6 DD3.11 | length 15.3
  Top Layer w0.2: v1(-27.45,-12.426) -27.4,-12.375 DD3.11 ; v1(-19.075,-5.025) -19.075,-4.525 DA2.6
  Bottom Layer w0.2: v1(-27.45,-12.426) -27.45,-12.05 -25.6,-10.2 -20.9,-10.2 -19.075,-8.375 v1(-19.075,-5.025)
NetDA3_3: DA3.3 DD3.20 | length 6.2
  Top Layer w0.2: DD3.20 -22.975,-15.6 -22.25,-16.325 -19.075,-16.325 DA3.3
NetDD1_4: DD1.4 XT1.3 | length 11.6
  Top Layer w0.25: XT1.3 -91.053,-41.859 -90.476,-42.436 v1(-90.407,-42.436) ; DD1.4 -84.492,-41.743 v1(-83.528,-40.78)
  Bottom Layer w0.25: v1(-90.407,-42.436) -85.184,-42.436 v1(-83.528,-40.78)
NetDD1_5: DD1.5 XT1.2 | length 9.3
  Top Layer w0.25: XT1.2 -90.528,-41.059 v1(-90.503,-41.084) ; DD1.5 -84.992,-41.372 -84.678,-41.059 v1(-84.678,-40.834)
  Bottom Layer w0.25: v1(-90.503,-41.084) -90.253,-40.834 v1(-84.678,-40.834)
NetDD1_9: DD1.9 R4.1 | length 1.8
  Top Layer w0.25: R4.1 -88.297,-43.759 DD1.9
NetDD1_11: DD1.11 R6.2 | length 1.8
  Top Layer w0.25: R6.2 -88.247,-44.759 DD1.11
NetDD1_25: DD1.25 pad.1@-80.817,-45.459 S5.6 | length 8.2
  Top Layer w0.25: DD1.25 -81.63,-44.759 -78.403,-47.986 S5.6
NetDD1_26: DD1.26 pad.1@-80.717,-44.209 S5.3 | length 4.4
  Top Layer w0.25: DD1.26 -80.053,-44.259 S5.3
NetDD2_2: DD2.2 S2.1 | length 36.2
  Top Layer w0.2: S2.1@-42.042,-35.484 -41.876,-35.65 v1(-39.975,-35.65) ; v1(-18.3,-32.025) -18.275,-32.05 DD2.2
  Top Layer w0.25: S2.1@-51.142,-35.484 S2.1@-42.042,-35.484
  Bottom Layer w0.2: v1(-39.975,-35.65) -39.6,-35.275 -25.828,-35.275 -23.503,-32.95 -23.22,-32.95 -21.851,-31.581 -18.744,-31.581 v1(-18.3,-32.025)
NetDD2_5: DD2.5 R8.1 | length 91.1
  Top Layer w0.2: v1(-93.95,-8.125) -93.95,-7.05 R8.1 ; v1(-84.425,-12.925) -84.4,-12.925 v1(-74.25,-23.075) ; v1(-18.3,-30.9) -17.95,-30.55 DD2.5
  Bottom Layer w0.2: v1(-93.95,-8.125) -89.15,-12.925 v1(-84.425,-12.925) ; v1(-74.25,-23.075) -63.525,-33.8 -41.35,-33.8 -40.275,-34.875 -25.994,-34.875 -23.669,-32.55 -23.386,-32.55 -22.016,-31.181 -18.856,-31.181 -18.575,-30.9 v1(-18.3,-30.9)
NetDD2_7: DD2.7 R18.1 XP1.15 | length 26.9
  Top Layer w0.2: v1(-18.325,-29.55) DD2.7 ; v1(-16.575,-34.375) -16.575,-34.7 -17.525,-35.65 -17.525,-39.275 R18.1 -16.925,-46.825 -16.925,-48.815 XP1.15
  Bottom Layer w0.2: v1(-18.325,-29.55) -18.058,-29.55 -16.6,-31.008 -16.6,-34.35 v1(-16.575,-34.375)
NetDD2_10: DD2.10 R12.1 | length 71.4
  Top Layer w0.2: R12.1 -78.675,-36.7 -75.025,-33.05 v1(-63.2,-33.05) ; v1(-20.2,-29.85) -20.2,-29.789 -19.511,-29.1 -19.501,-29.1 -19.15,-28.749 -19.15,-28.739 -18.511,-28.1 -16.9,-28.1 DD2.10
  Bottom Layer w0.2: v1(-63.2,-33.05) -62.85,-33.4 -41.184,-33.4 -40.109,-34.475 -26.159,-34.475 -23.834,-32.15 -23.551,-32.15 -21.251,-29.85 v1(-20.2,-29.85)
NetDD2_11: DD2.11 XP14.1 | length 20.7
  Top Layer w0.2: DD2.11 -14.15,-27.55 -1.75,-15.15 XP14.1
NetDD2_12: DD2.12 S5.5 | length 81.7
  Top Layer w0.2: S5.5@-76.954,-50.908 -76.625,-50.579 v1(-76.625,-49.925) ; DD2.12 -15.95,-27.05 v1(-15.5,-26.6)
  Bottom Layer w0.2: v1(-76.625,-49.925) -73.525,-53.025 -41.725,-53.025 -24.25,-35.55 -16.084,-35.55 -14.6,-34.066 -14.6,-27.5 v1(-15.5,-26.6)
NetDD2_13: DD2.13 S5.2 | length 74.3
  Top Layer w0.2: S5.2 -76.653,-44.728 v1(-76.6,-44.675) ; v1(-62.8,-35.25) -62.625,-35.25 v1(-60.025,-32.65) ; v1(-23.375,-21.775) -21.925,-20.325 -19.336,-20.325 -18.325,-21.336 DD2.13
  Bottom Layer w0.2: v1(-76.6,-44.675) -72.925,-41 -68.55,-41 v1(-62.8,-35.25) ; v1(-60.025,-32.65) -49.15,-21.775 v1(-23.375,-21.775)
NetDD2_14: DD2.14 S1.1 | length 73.2
  Top Layer w0.2: S1.1@-80.942,-35.459 v1(-79.116,-35.459) ; v1(-73.825,-35.7) -72.083,-35.7 -71.842,-35.459 -71.451,-35.85 -61.85,-35.85 v1(-58.55,-32.55) ; v1(-22.7,-22.35) -21.075,-20.725 -19.501,-20.725 -18.8,-21.426 -18.8,-25.55 DD2.14
  Bottom Layer w0.2: v1(-79.116,-35.459) -78.875,-35.7 v1(-73.825,-35.7) ; v1(-58.55,-32.55) -48.375,-22.375 -22.725,-22.375 v1(-22.7,-22.35)
NetDD2_15: DD2.15 DD3.15 | length 14.1
  Top Layer w0.2: v1(-25.65,-15.75) -25.475,-15.575 DD3.15 ; v1(-19.4,-21.675) -19.375,-21.7 -19.375,-25.475 -19.35,-25.5 -19.375,-25.525 DD2.15
  Bottom Layer w0.2: v1(-25.65,-15.75) -25.526,-15.75 -19.375,-21.901 -19.374,-21.9 -19.4,-21.874 v1(-19.4,-21.675)
NetDD2_16: DD2.16 DD3.16 | length 13.4
  Top Layer w0.2: DD3.16 -24.975,-18.1 -24.175,-18.9 v1(-23.7,-18.9) ; v1(-20.175,-22.175) -20.175,-22.226 -19.825,-22.576 DD2.16
  Bottom Layer w0.2: v1(-23.7,-18.9) -23.501,-18.9 -20.226,-22.175 v1(-20.175,-22.175)
NetDD2_17: DD2.17 DD3.17 | length 12.7
  Top Layer w0.2: DD3.17 -24.475,-17.425 -24.3,-17.6 v1(-24.3,-17.825) ; v1(-20.95,-22.551) -20.225,-23.276 -20.225,-24.524 -20.325,-24.623 DD2.17
  Bottom Layer w0.2: v1(-24.3,-17.825) -24.3,-19.275 -20.95,-22.625 v1(-20.95,-22.551)
NetDD2_18: DD2.18 DD3.19 | length 13.9
  Top Layer w0.2: v1(-23.475,-16.3) DD3.19 ; v1(-20.85,-23.925) -20.85,-25.55 DD2.18
  Bottom Layer w0.2: v1(-23.475,-16.3) -23.475,-16.751 -18.675,-21.551 -18.675,-22.125 -20.475,-23.925 v1(-20.85,-23.925)
NetDD2_19: DD2.19 DD3.14 | length 14.6
  Top Layer w0.2: v1(-27.075,-14.375) -27.075,-14.1 -26.85,-13.875 DD3.14 ; v1(-21.775,-22.9) -21.775,-23.849 -21.325,-24.299 DD2.19
  Bottom Layer w0.2: v1(-27.075,-14.375) -27.075,-17.126 -21.775,-22.426 v1(-21.775,-22.9)
NetDD2_20: DD2.20 XT3.3 | length 60.2
  Top Layer w0.2: v1(-59.575,-45.675) -59.575,-35.2 v1(-56.85,-32.475) ; XT3.3 -57.717,-49.484 -57.717,-47.767 v1(-57.55,-47.6) ; v1(-22.5,-23.351) -22.5,-23.689 -21.825,-24.364 DD2.20
  Bottom Layer w0.2: v1(-59.575,-45.675) -57.65,-47.6 v1(-57.55,-47.6) ; v1(-56.85,-32.475) -47.3,-22.925 -22.974,-22.925 -22.949,-22.95 -22.901,-22.95 v1(-22.5,-23.351)
NetDD2_21: DD2.21 XP3.1 | length 40.4
  Top Layer w0.2: DD2.21 -22.325,-24.43 -23.975,-22.78 -23.975,-21.526 -22.22,-19.771 -19.279,-19.771 v1(-13.35,-25.7)
  Bottom Layer w0.2: v1(-13.35,-25.7) -12.7,-26.35 -1.275,-26.35 -0.525,-27.1 -0.525,-33.82 XP3.1
NetDD2_22: DD2.22 XP4.1 | length 27.6
  Top Layer w0.2: DD2.22 -22.825,-26.45 -22.25,-27.025 -18.3,-27.025 -17.075,-25.8 -15.3,-25.8 v1(-14.375,-26.725) ; v1(-6.8,-32.535) XP4.1
  Bottom Layer w0.2: v1(-14.375,-26.725) -13.2,-27.9 -11.435,-27.9 v1(-6.8,-32.535)
NetDD2_25: DD2.25 XP8.1 | length 56.3
  Top Layer w0.2: v1(-34.375,-41.75) -33.825,-42.275 -23.486,-42.275 -22.55,-41.339 v1(-22.55,-40.775) ; v1(-34.375,-36.275) -34.35,-33.45 v1(-34.325,-33.475) ; v1(-27.875,-26.725) -26.85,-26.725 -26.525,-27.05 DD2.25
  Bottom Layer w0.2: v1(-34.375,-41.75) v1(-34.375,-36.275) ; v1(-34.325,-33.475) -34.325,-30.175 -30.875,-26.725 v1(-27.875,-26.725) ; v1(-22.55,-40.775) -2.4,-40.775 XP8.1
NetDD2_26: DD2.26 XP16.1 | length 52.6
  Top Layer w0.2: v1(-33.175,-41.675) -33.15,-41.7 -32.75,-41.3 v1(-23.4,-41.3) ; v1(-33.15,-33.5) -33.125,-33.525 v1(-33.125,-36.25) ; v1@-27.875,-27.5 v1(-27.875,-27.55) DD2.26@-25.35,-27.55 ; DD2.26@-25.35,-27.5 DD2.26
  Bottom Layer w0.2: v1(-33.175,-41.675) -33.125,-41.625 v1(-33.125,-36.25) ; v1(-33.15,-33.5) -33.15,-30.275 -30.425,-27.55 v1(-27.875,-27.55) ; v1(-23.4,-41.3) -22.035,-42.665 XP16.1
NetDD2_29: DD2.29 XP10.1 | length 28.8
  Top Layer w0.2: DD2.29 -24.15,-29.05 -23.6,-28.5 v1(-23.6,-27.825)
  Bottom Layer w0.2: v1(-23.6,-27.825) -23.375,-27.825 -18.5,-22.95 -7.435,-22.95 XP10.1
NetDD2_30: DD2.30 XP15.1 | length 28.1
  Top Layer w0.2: DD2.30 -23.575,-29.55 v1(-23.225,-29.2)
  Bottom Layer w0.2: v1(-23.225,-29.2) -23.225,-28.325 -18.25,-23.35 -5.295,-23.35 XP15.1
NetDD2_31: DD2.31 XP11.1 | length 27
  Top Layer w0.2: DD2.31 -22.85,-30.05 -21.55,-28.75 v1(-21.55,-28.425)
  Bottom Layer w0.2: v1(-21.55,-28.425) -21.55,-28.326 -17.849,-24.625 -4.03,-24.625 XP11.1
NetDD2_32: DD2.32 XP5.1 | length 26
  Top Layer w0.2: DD2.32 -22.675,-30.55 -20.025,-27.9 v1(-20.025,-27.65)
  Bottom Layer w0.2: v1(-20.025,-27.65) -17.4,-25.025 -1.89,-25.025 XP5.1
NetDD2_33: DD2.33 XP6.1 | length 26.7
  Top Layer w0.2: DD2.33 -24.149,-31.05 -24.049,-30.95 -22.325,-30.95 -19.875,-28.5 v1(-19.75,-28.5)
  Bottom Layer w0.2: v1(-19.75,-28.5) -19.75,-28.375 -16.925,-25.55 -14.65,-25.55 -12.775,-27.425 XP6.1
NetDD2_34: DD2.34 XP1.7 | length 23.6
  Top Layer w0.2: v1(-26.135,-33.3) -25.625,-33.3 -25.025,-33.9 v1(-25.025,-37.225) ; DD2.34 v1(-23.8,-31.55)
  Bottom Layer w0.2: v1(-26.135,-33.3) -25.55,-33.3 v1(-23.8,-31.55) ; XP1.7 -27.125,-48.775 -27.125,-39.25 -25.025,-37.15 v1(-25.025,-37.225)
NetDD2_37: DD2.37 XP1.9 | length 16.7
  Top Layer w0.2: v1(-24.125,-36.727) -24.125,-35.905 -23.825,-35.604 DD2.37
  Bottom Layer w0.2: v1(-24.125,-36.727) -24.125,-39.577 -24.39,-39.841 -24.39,-49.015 -23.38,-50.025 XP1.9
NetDD2_38: DD2.38 XP7.1 | length 27.1
  Top Layer w0.2: v1(-23.475,-36.225) -23.325,-36.075 DD2.38
  Bottom Layer w0.2: v1(-23.475,-36.225) -23.475,-36.45 -23.175,-36.75 -8.535,-36.75 XP7.1
NetDD2_39: DD2.39 XT3.5 | length 49.2
  Top Layer w0.2: XT3.5 -58.767,-40.492 -56.025,-37.75 -25.349,-37.75 -25.274,-37.825 -24.175,-37.825 -22.825,-36.475 DD2.39
NetDD2_40: DD2.40 XT3.1 | length 48.3
  Top Layer w0.2: XT3.1 -56.767,-39.492 -55.459,-38.184 -25.48,-38.184 -25.439,-38.225 -23.925,-38.225 -22.325,-36.625 DD2.40
NetDD2_41: DD2.41 XT3.4 | length 49.3
  Top Layer w0.2: XT3.4 -58.217,-49.484 -58.217,-41.167 v1(-58.075,-41.025) ; v1(-55.575,-39.325) -54.834,-38.584 -25.646,-38.584 -25.605,-38.625 -23.759,-38.625 -21.825,-36.691 DD2.41
  Bottom Layer w0.2: v1(-58.075,-41.025) -56.375,-39.325 v1(-55.575,-39.325)
NetDD2_42: DD2.42 XT3.2 | length 50.8
  Top Layer w0.2: XT3.2 -57.267,-50.183 -56.925,-50.525 -56.425,-50.525 -56.175,-50.275 -56.175,-40.925 -54.234,-38.984 -25.812,-38.984 -25.771,-39.025 -23.45,-39.025 -21.375,-36.95 -21.375,-34.075 DD2.42
NetDD2_43: DD2.43 S3.1 | length 89.9
  Top Layer w0.2: S3.1@-86.192,-12.384 S3.1@-86.192,-3.284 ; S3.1@-85.767,-12.384 -85.767,-12.56 -85.891,-12.685 -75.475,-23.101 v1(-75.475,-23.125) ; v1(-36.725,-39.775) -36.35,-39.4 -25.961,-39.4 -25.936,-39.425 -23.284,-39.425 -20.975,-37.116 -20.975,-35.425 -20.825,-35.275 DD2.43
  Bottom Layer w0.2: v1(-75.475,-23.125) -64.4,-34.2 -42.3,-34.2 v1(-36.725,-39.775)
NetDD2_45: DD2.45 S4.1 | length 84.6
  Top Layer w0.2: S4.1@-86.192,-21.325 -86.192,-23.083 v1(-86.15,-23.125) ; v1(-86.175,-28.625) -86.175,-30.408 -86.192,-30.425 -85.308,-31.309 -81.516,-31.309 v1(-81.325,-31.5) ; v1(-36.7,-40.825) -36.575,-40.7 -23.349,-40.7 -19.725,-37.076 -19.725,-34.924 -19.775,-34.874 -19.775,-34.075 DD2.45
  Bottom Layer w0.2: v1(-86.175,-28.625) -86.15,-28.6 v1(-86.15,-23.125) ; v1(-81.325,-31.5) -78.2,-34.625 -43,-34.625 -36.8,-40.825 v1(-36.7,-40.825)
NetDD2_46: DD2.46 XP2.1 | length 23.2
  Top Layer w0.2: v1(-19.35,-37.55) -19.325,-37.525 DD2.46
  Bottom Layer w0.2: v1(-19.35,-37.55) -6.795,-37.55 XP2.1
NetDD3_13: DD3.13 R11.1 | length 10.5
  Top Layer w0.2: R11.1 -28.6,-13.75 -27.525,-13.75 -27.201,-13.426 -26.801,-13.426 -26.75,-13.375 DD3.13
NetHL4_A: HL4.A R2.2 | length 4.7
  Top Layer w0.2: R2.2 -10.3,-1.4 -9.2,-0.3 HL4.A
NetHL5_A: HL5.A R8.2 | length 3.5
  Top Layer w0.2: HL5.A -95.85,-3.5 R8.2
NetHL6_A: HL6.A R11.2 | length 3.5
  Top Layer w0.2: R11.2 -34.325,-2.974 HL6.A
NetJMP1_1: JMP1.1 VD1.3 | length 6.1
  Top Layer w0.2: JMP1.1@-95.4,-25.575 v1(-95.35,-25.575) JMP1.1 -94.15,-25.575
  Top Layer w0.5: VD1.3 -95.325,-22.1 JMP1.1
NetLCD1_K: LCD1.K R12.2 | length 8.2
  Top Layer w0.25: R12.2@-83.703,-35.409 -80.403,-32.109 LCD1.K
NetS5_1: S5.1 XP22.1 | length 17.1
  Top Layer w0.25: XP22.1@-89.359,-52.234 -85.234,-48.109 v1(-81.253,-48.109) ; v1(-77.553,-48.084) -77.078,-48.084 S5.1
  Bottom Layer w0.25: v1(-81.253,-48.109) -81.228,-48.084 v1(-77.553,-48.084)
NetS5_4: S5.4 XP23.1 | length 14
  Top Layer w0.25: XP23.1@-86.819,-52.234 -85.569,-50.984 -81.753,-50.984 -80.128,-52.609 -75.803,-52.609 -74.903,-51.709 S5.4
NetVD1_1: VD1.1 XT2.1 | length 14.8
  Top Layer w0.5: VD1.1 -98.125,-18.27 -93.625,-13.77 -93.625,-10 -94.691,-8.934 XT2.1
VCC: C9.2 C10.2 C16.1 C17.1 C18.1 C19.1 C20.1 C21.1 DA3.1 DD2.1 DD2.9 DD2.24 DD2.36 DD2.48 DD3.23 JMP1.2 LCD1.A R18.2 XP1.1 XP13.1 XP21.1 | length 201.5
  Top Layer w0.2: DD3.23 -20.5,-13.375 C10.2
  Top Layer w0.3: XP1.1 -32.275,-48.805 -32.275,-47.1 -27.925,-42.75 R18.2 -22.6,-42.025 -18.325,-37.75 DD2.48 -18.325,-33 ; C17.1 -27.675,-32.55 DD2.36 -23.925,-32.55 -23.525,-32.95 -21.25,-32.95 -19.95,-31.65 -19.275,-31.65 -19.025,-31.4 ; C18.1 -24.925,-22.475 -23.825,-23.575 DD2.24 ; C10.2 -20.2,-13.625 DA3.1 -17.4,-13.625 -17.05,-13.975 -17.05,-18.125 -17.9,-18.975 C9.2@-17.9,-19.475 ; C20.1 -15.196,-32.55 DD2.1 -17.875,-32.55 -18.325,-33 ; C21.1@-14.175,-28.55 DD2.9 -18.315,-28.55 -19.025,-29.26 -19.025,-31.4 ; -19.025,-31.4 -19.025,-32.3 -18.325,-33
  Top Layer w0.5: JMP1.2 -87.45,-25.575 -84.241,-28.784 v1(-84.241,-30.525) -84.082,-30.684 -47.517,-30.684 LCD1.A@-46.103,-32.097 ; LCD1.A@-46.092,-32.085 -44.606,-30.6 -39.95,-30.6 -37.925,-32.625 C16.1 ; C17.1 C16.1 ; C9.2@-18.225,-19.221 -22.96,-19.221 -24.925,-21.186 C18.1 -27.769,-22.219 -29.25,-23.7 C16.1 ; C9.2 -15.296,-21.7 -11.265,-21.7 XP13.1
  Bottom Layer w0.5: XP21.1@-84.279,-52.234 -82.392,-50.347 -82.392,-37.909 -84.525,-35.776 -84.525,-30.79 -84.26,-30.525 v1(-84.241,-30.525)
  other v1: -93.95,-25.575
pads on no net: DA3.4 DD1.1 DD1.2 DD1.10 DD1.12 DD1.13 DD1.14 DD1.15 DD1.16 DD1.17 DD1.18 DD1.19 DD1.20 DD1.21 DD1.22 DD1.23 DD1.24 DD1.27 DD1.28 DD2.27 DD2.28 DD3.5 DD3.9 DD3.10 DD3.18 DD3.21 DD3.22 DD3.24 LCD1. XP1.2 XP1.3 XP1.5 XP1.11 XP1.13 XP1.17 XP1.19 XT1.4
copper on no net:
  other v2: -98.242,20.666 -2.242,20.672

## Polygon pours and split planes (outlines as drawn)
GND on Bottom Layer "Bot Layer-GND" (solid, pour order 7): -98.242,-53.834 cw(c-98.242,-51.334) -100.742,-51.334 -100.745,-0.001 0.258,0.006 0.258,-51.328 cw(c-2.242,-51.328) -2.242,-53.828
GND on Top Layer "Top Layer-GND" (solid, pour order 6): -98.242,-53.834 cw(c-98.242,-51.334) -100.742,-51.334 -100.745,-0.001 0.258,0.006 0.258,-51.328 cw(c-2.242,-51.328) -2.242,-53.828

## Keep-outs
Keep-Out Layer:
  lines w0.1: -100.747,20.667 -100.742,-51.334 ccw(c-98.242,-51.334) -98.242,-53.834 -2.242,-53.834 ; -100.742,20.667 cw(c-98.242,20.667) -98.242,23.167 ; -98.247,23.166 -2.242,23.166 ; -2.242,-53.828 ccw(c-2.242,-51.328) 0.258,-51.328 0.258,20.673 ccw(c-2.242,20.673) -2.242,23.173

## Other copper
Top Layer:
  rectangle net GND: -14.4,0 -10.4,22.8
  rectangle net GND: -21,18.8 -10.4,22.8
  rectangle net GND: -19.05,2.4 -16.05,3.508
  region: 3755 vertices and 7 holes, not listed, extent -80.22,3.546 -72.767,15.879
  region net GND: -16.05,3.508 -16.375,4.4 -16.4,3.5
  text "STM32L+AX5043" at -41.425,2.825 h3
  text "DevKitSTM_r2" at -50.955,-48.096 h1
  text "05.02.18" at -50.905,-50.821 h1

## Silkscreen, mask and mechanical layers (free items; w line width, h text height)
Top Overlay:
  drawing of 11 lines, arcs and shapes, not listed
  text "Development Kit" at -68.625,2.875 h4
  text "EXT ANT" at -9.1,0.975 h1
  text "Tx" at -35.175,0.7 h1
  text "POWER" at -99.775,-2.05 h1
  text "3V3" at -5.111,-10.105 h1 r315
  text "SB3" at -89.8,-12.525 h1
  text "PA1" at -5.111,-12.645 h1 r315
  text "EXT BAT" at -100.075,-15.1 h1
  text "PA8" at -4.993,-15.185 h1 r315
  text "PA9" at -5.111,-17.725 h1 r315
  text "PA10" at -5.568,-19.69 h1 r315
  text "PA11" at -5.586,-22.33 h1 r315
  text "PA12" at -5.543,-24.795 h1 r315
  text "PA15" at -5.636,-27.36 h1 r315
  text "PB9" at -4.993,-30.425 h1 r315
  text "SB4" at -89.75,-30.55 h1
  text "PB10" at -5.636,-32.44 h1 r315
  text "PB11" at -5.443,-35.055 h1 r315
  text "PB12" at -5.636,-37.52 h1 r315
  text "PB13" at -5.593,-39.96 h1 r315
  text "SB2" at -47.717,-42.159 h1
  text "SB1" at -77.367,-42.209 h1
  text "GND" at -5.111,-42.985 h1 r315
  text "DEBUG" at -13.15,-43.325 h1
  text "J1" at -73.342,-48.509 h1
  text "1" at -80.267,-50.284 h1
  text "2" at -73.417,-50.359 h1
  text "GND" at -91.372,-51.123 h1 r45
  text "3V3" at -83.711,-51.134 h1 r45
  text "URX" at -88.926,-51.284 h1 r45
  text "UTX" at -86.39,-51.291 h1 r45
Top Solder:
  drawing of 3 lines, arcs and shapes, not listed
  text "STM32L+AX5043" at -41.425,2.825 h3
